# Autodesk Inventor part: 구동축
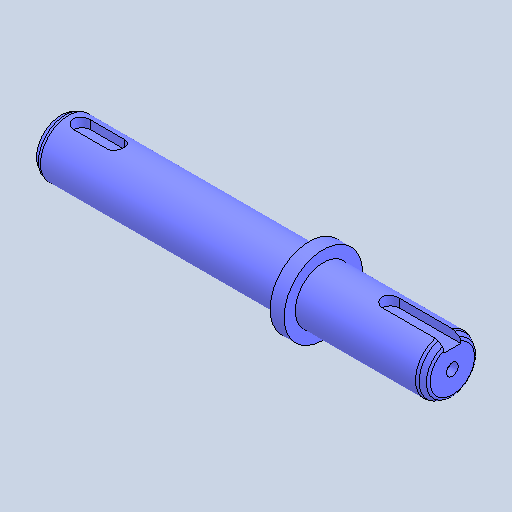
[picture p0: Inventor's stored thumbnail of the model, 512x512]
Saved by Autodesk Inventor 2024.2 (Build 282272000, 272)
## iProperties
Created: 2026-01
Part Number: 구동축
Material: 강철, 탄소
Document SubType Name: Modeling
Designer: home
Density: 7.85 g/cm^3
Appearance: 기본값
Author: jhkim
Sending System: Autodesk Inventor 2026
Preprocessor: ST-DEVELOPER v20.1
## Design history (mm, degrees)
feature "솔리드1"
node "솔리드2"
